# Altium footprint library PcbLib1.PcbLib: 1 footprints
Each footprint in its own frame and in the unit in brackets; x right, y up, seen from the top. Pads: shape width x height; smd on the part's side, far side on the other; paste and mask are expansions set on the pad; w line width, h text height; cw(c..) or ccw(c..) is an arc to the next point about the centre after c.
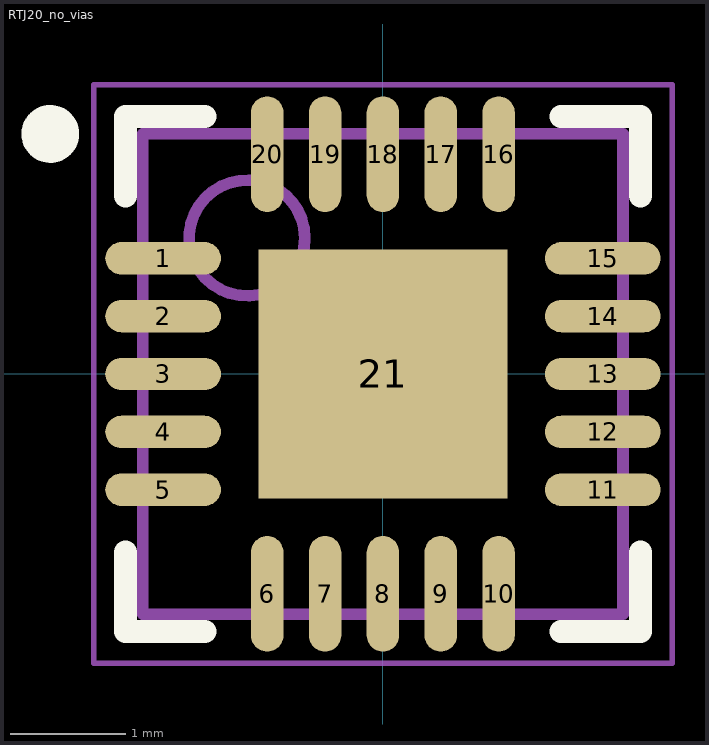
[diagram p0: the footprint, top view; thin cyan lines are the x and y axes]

## RTJ20_no_vias [mm]
pads (21):
  oval 1x0.28 smd paste-0.025 mask+0.07: 1(-1.9,1) 2(-1.9,0.5) 3(-1.9,0) 4(-1.9,-0.5) 5(-1.9,-1) 11(1.9,-1) 12(1.9,-0.5) 13(1.9,0) 14(1.9,0.5) 15(1.9,1)
  oval 0.28x1 smd paste-0.025 mask+0.07: 6(-1,-1.9) 7(-0.5,-1.9) 8(0,-1.9) 9(0.5,-1.9) 10(1,-1.9) 16(1,1.9) 17(0.5,1.9) 18(0,1.9) 19(-0.5,1.9) 20(-1,1.9)
  rect 2.15x2.15 smd paste-1.075 mask+0.07: 21(0,0)
Top Overlay:
  circle w0.25: c-2.875,2.075 r0.125
  lines w0.2: -2.225,-1.54 -2.225,-2.225 -1.54,-2.225 ; -2.225,1.54 -2.225,2.225 -1.54,2.225 ; 1.54,-2.225 2.225,-2.225 2.225,-1.54 ; 1.54,2.225 2.225,2.225 2.225,1.54
Top Paste:
  rectangle: 0.15,-1.05 1.05,-0.15
  region: -0.15,-0.15 -1.05,-0.15 -1.05,-1.05 -0.15,-1.05
  region: -0.15,1.05 -1.05,1.05 -1.05,0.15 -0.15,0.15
  rectangle: 0.15,0.15 1.05,1.05
M5 Assembly Top:
  circle w0.1: c-1.175,1.175 r0.5
  lines w0.1: -2.075,-2.075 2.075,-2.075 2.075,2.075 -2.075,2.075 -2.075,-2.075
M15  Courtyards Top:
  lines w0.05: -2.5,-2.5 2.5,-2.5 2.5,2.5 -2.5,2.5 -2.5,-2.5
  lines w0.1: -0.5,0 0.5,0 ; 0,-0.5 0,0.5
3D body: height 0.8, standoff 0, extent -2.075,-2.075 2.075,2.075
